// Mitsubishi GX Works2 project: 14.控制方式选择2   PLC: FX3U/FX3UC

PROGRAM MAIN
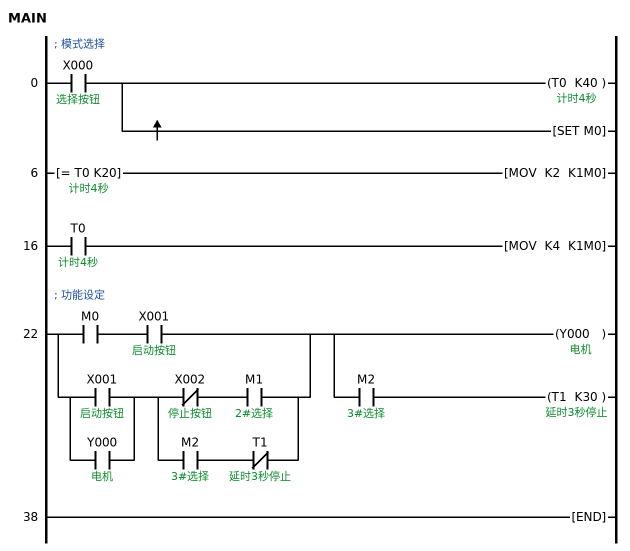
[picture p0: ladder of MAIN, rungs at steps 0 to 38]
; 模式选择
0     LD      X000  ; 选择按钮
      OUT     T0 K40  ; 计时4秒
      MEP
      SET     M0
        [note] ↑：线上沿。每次只会置位M0 1次
6     LD=     T0 K20  ; 计时4秒
      MOV     K2 K1M0
        [note] 置位m1,复位其他
16    LD      T0  ; 计时4秒
      MOV     K4 K1M0
        [note] 置位m2,复位其他
; 功能设定
22    LD      M0
      AND     X001  ; 启动按钮
      LD      X001  ; 启动按钮
      OR      Y000  ; 电机
      LDI     X002  ; 停止按钮
      AND     M1  ; 2#选择
      LD      M2  ; 3#选择
      ANI     T1  ; 延时3秒停止
      ORB
      ANB
      ORB
      OUT     Y000  ; 电机
      AND     M2  ; 3#选择
      OUT     T1 K30  ; 延时3秒停止
38    END
END_PROGRAM

// device comments not shown above
Y001  ; 2#电机
Y002  ; 3#电机
